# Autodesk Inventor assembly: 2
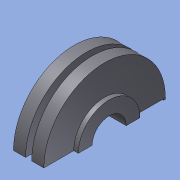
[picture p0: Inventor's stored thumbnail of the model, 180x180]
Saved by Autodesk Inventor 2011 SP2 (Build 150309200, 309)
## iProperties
Created: 2013-10
Part Number: 2
Document SubType Name: Schweißkonstruktion
Weld Material: Geschweißter Stahl (weich)
Mass: 320871 g
Surface Area: 13027 cm^2
Volume: 40927.5 cm^3
Density: 7.84 g/cm^3
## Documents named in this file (2)
- C:\VaultWS\Designs\MinPro\Arbeitsordner\3_Pers_Arbeitso\Schmid\Kettenrad 55227341100000 Beispiel\2.iam
- C:\VaultWS\Designs\MinPro\Arbeitsordner\3_Pers_Arbeitso\Schmid\Kettenrad 55227341100000 Beispiel\1.ipt
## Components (1 placed, 1 different names)
1. 1:1
